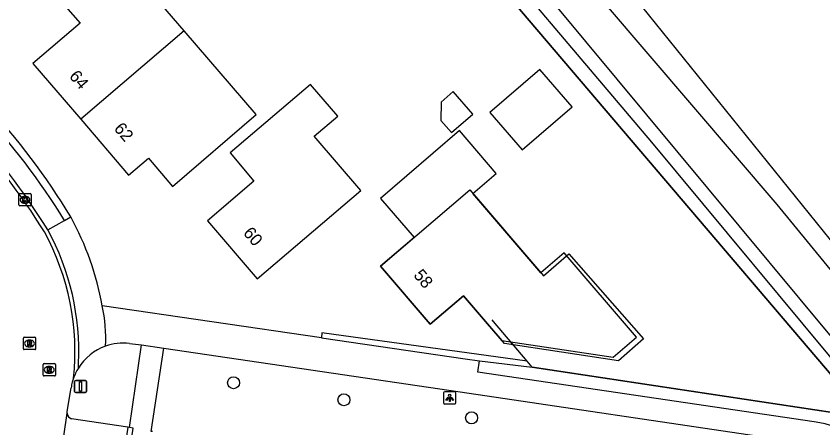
# Model space of a CAD drawing. Extents: x 164150 to 165261, y 382513 to 383432.
# Drawn here: x 164601.5 to 164667.2, y 383211.9 to 383245.5 of the extents above; entities that cross this region are included whole.
import ezdxf

# ---------------------------------------------------------------- set-up
doc = ezdxf.new("R2010")
doc.units = 0
for name, color, linetype in [('IMGEO_Afsluitpaal', 7, 'Continuous'), ('IMGEO_Boom', 7, 'Continuous'), ('IMGEO_Groenvoorziening', 7, 'Continuous'), ('IMGEO_Haag', 7, 'Continuous'), ('IMGEO_Hek', 7, 'Continuous'), ('IMGEO_Kolk', 7, 'Continuous'), ('IMGEO_Lichtpunt', 7, 'Continuous'), ('IMGEO_Pand', 7, 'Continuous'), ('IMGEO_Pand_nummerreeks', 7, 'Continuous'), ('IMGEO_Pand_vergunning_verleend', 7, 'Continuous'), ('IMGEO_Parkeervlak_open', 7, 'Continuous'), ('IMGEO_Rijbaan_lokaal_open', 7, 'Continuous'), ('IMGEO_Rioolput', 7, 'Continuous'), ('IMGEO_Voetpad_open', 7, 'Continuous'), ('IMGEO_Waterloop', 7, 'Continuous')]:
    doc.layers.add(name, color=color, linetype=linetype)

msp = doc.modelspace()

# ---------------------------------------------------------------- linework, layer by layer
at = {"layer": 'IMGEO_Afsluitpaal'}
for p, q in [((164606.376, 383215.801), (164607.166, 383215.801)), ((164607.166, 383215.801), (164606.376, 383215.801)), ((164606.276, 383214.901), (164606.276, 383215.701)), ((164606.276, 383215.701), (164606.276, 383214.901)), ((164607.266, 383215.701), (164607.266, 383214.901)), ((164607.266, 383214.901), (164607.266, 383215.701)), ((164607.166, 383214.801), (164606.376, 383214.801)), ((164606.376, 383214.801), (164607.166, 383214.801))]:
    msp.add_line(p, q, dxfattribs=at)
msp.add_lwpolyline([(164606.696, 383215.676), (164606.846, 383215.676), (164606.846, 383214.926), (164606.696, 383214.926), (164606.696, 383215.676)], dxfattribs=at)
for centre, start, end in [((164606.376, 383215.701), 90, 180), ((164606.376, 383215.701), 90, 180), ((164607.166, 383215.701), 0, 90), ((164607.166, 383215.701), 360, 90), ((164606.376, 383214.901), 180, 270), ((164606.376, 383214.901), 180, 270), ((164607.166, 383214.901), 270, 0), ((164607.166, 383214.901), 270, 0)]:
    msp.add_arc(centre, 0.1, start, end, dxfattribs=at)
at = {"layer": 'IMGEO_Boom'}
for centre in [(164619.226, 383215.605), (164628.209, 383214.22), (164638.607, 383212.751)]:
    msp.add_circle(centre, 0.489, dxfattribs=at)
at = {"layer": 'IMGEO_Groenvoorziening'}
for points in [[(164566.305, 383344.311), (164569.232, 383342.658), (164579.791, 383329.652), (164603.14, 383303.958), (164617.977, 383286.766), (164648.404, 383251.254), (164673.485, 383220.184), (164709.708, 383176.739), (164710.441, 383175.86), (164752.593, 383124.39), (164776.716, 383094.655), (164796.852, 383070.221), (164805.188, 383059.841), (164822.836, 383038.617), (164858.114, 382995.014), (164877.754, 382971.302), (164899.005, 382944.896), (164903.538, 382938.379)], [(164565.515, 383339.104), (164586.345, 383315.663), (164606.03, 383291.593), (164619.657, 383274.842), (164653.254, 383235.189), (164669.707, 383215.37), (164689.184, 383191.909), (164697.544, 383182.287), (164699.35, 383180.017), (164699.148, 383178.489), (164689.54, 383169.792), (164688.541, 383168.421), (164688.591, 383167.263)], [(164643.541, 383216.874), (164670.853, 383212.753), (164601.938, 383293.634), (164580.845, 383318.389), (164573.491, 383327.02), (164568.932, 383331.938), (164563.693, 383332.71)]]:
    msp.add_lwpolyline(points, dxfattribs=at)
at = {"layer": 'IMGEO_Haag'}
for points in [[(164643.541, 383216.874), (164643.122, 383217.367), (164626.412, 383219.679), (164626.392, 383219.249)], [(164639.25, 383217.382), (164643.541, 383216.874)]]:
    msp.add_lwpolyline(points, dxfattribs=at)
at = {"layer": 'IMGEO_Hek'}
msp.add_lwpolyline([(164546.01, 383335.315), (164546.486, 383335.245), (164563.693, 383332.71), (164568.932, 383331.938), (164573.491, 383327.02), (164580.845, 383318.389), (164601.938, 383293.634), (164670.853, 383212.753), (164643.541, 383216.874), (164643.122, 383217.367), (164640.381, 383220.598), (164640.269, 383220.73)], dxfattribs=at)
at = {"layer": 'IMGEO_Kolk'}
for p, q in [((164601.745, 383230.077), (164601.745, 383230.929)), ((164601.82, 383231.003), (164602.672, 383231.003)), ((164602.746, 383230.929), (164602.746, 383230.077)), ((164602.233, 383230.783), (164602.258, 383230.783)), ((164602.672, 383230.003), (164601.82, 383230.003)), ((164602.256, 383230.223), (164602.231, 383230.223))]:
    msp.add_line(p, q, dxfattribs=at)
for points in [[(164601.745, 383230.077), (164601.745, 383230.929)], [(164601.82, 383231.003), (164602.672, 383231.003)], [(164602.746, 383230.929), (164602.746, 383230.077)], [(164602.066, 383230.703), (164602.189, 383230.703), (164602.189, 383230.552), (164602.319, 383230.703), (164602.483, 383230.703), (164602.337, 383230.552), (164602.49, 383230.303), (164602.338, 383230.303), (164602.253, 383230.467), (164602.189, 383230.4), (164602.189, 383230.303), (164602.066, 383230.303), (164602.066, 383230.703)], [(164602.672, 383230.003), (164601.82, 383230.003)]]:
    msp.add_lwpolyline(points, dxfattribs=at)
for centre, start, end in [((164601.822, 383230.927), 91.55205, 178.44795), ((164601.822, 383230.927), 91.55205, 178.44795), ((164602.67, 383230.927), 1.55205, 88.44795), ((164602.67, 383230.927), 1.55205, 88.44795), ((164601.822, 383230.079), 181.55205, 268.44795), ((164601.822, 383230.079), 181.55205, 268.44795), ((164602.67, 383230.079), 271.55205, 358.44795), ((164602.67, 383230.079), 271.55205, 358.44795)]:
    msp.add_arc(centre, 0.0765, start, end, dxfattribs=at)
for centre, major_axis, ratio, start_param, end_param in [((164602.232, 383230.503), (-0.387, 0.002), 0.722429, 4.712389, 7.853982), ((164602.257, 383230.503), (-0.39, 0.002), 0.717154, 1.570796, 4.712389)]:
    msp.add_ellipse(centre, major_axis=major_axis, ratio=ratio, start_param=start_param, end_param=end_param, dxfattribs=at)
at = {"layer": 'IMGEO_Lichtpunt'}
for p, q in [((164636.323, 383214.776), (164636.323, 383213.969)), ((164636.323, 383214.776), (164636.323, 383213.969)), ((164637.225, 383214.871), (164636.417, 383214.871)), ((164637.225, 383214.871), (164636.417, 383214.871)), ((164637.319, 383213.969), (164637.319, 383214.776)), ((164637.319, 383213.969), (164637.319, 383214.776)), ((164636.417, 383213.875), (164637.225, 383213.875)), ((164636.417, 383213.875), (164637.225, 383213.875))]:
    msp.add_line(p, q, dxfattribs=at)
for points in [[(164636.697, 383214.44), (164636.736, 383214.412), (164636.548, 383214.15), (164636.51, 383214.177), (164636.697, 383214.44)], [(164636.799, 383214.392), (164636.846, 383214.392), (164636.846, 383214.07), (164636.799, 383214.07), (164636.799, 383214.392)], [(164636.909, 383214.412), (164636.947, 383214.439), (164637.134, 383214.177), (164637.095, 383214.149), (164636.909, 383214.412)]]:
    msp.add_lwpolyline(points, dxfattribs=at)
msp.add_circle((164636.822, 383214.574), 0.0994, dxfattribs=at)
for centre, start, end in [((164636.417, 383214.776), 90, 180), ((164636.417, 383214.776), 90, 180), ((164637.225, 383214.776), 0, 90), ((164637.225, 383214.776), 0, 90), ((164636.417, 383213.969), 180, 270), ((164636.417, 383213.969), 180, 270), ((164637.225, 383213.969), 270, 0), ((164637.225, 383213.969), 270, 360)]:
    msp.add_arc(centre, 0.0946, start, end, dxfattribs=at)
at = {"layer": 'IMGEO_Pand'}
for points in [[(164615.196, 383244.255), (164609.326, 383251.083), (164604.764, 383247.162), (164606.73, 383244.876), (164602.89, 383241.599), (164606.788, 383237.05)], [(164615.196, 383244.255), (164606.788, 383237.05)], [(164606.788, 383237.05), (164610.685, 383232.501), (164612.288, 383233.879), (164614.258, 383231.586), (164621.06, 383237.434), (164615.196, 383244.255)], [(164640.092, 383237.6), (164642.715, 383234.558), (164646.787, 383238.07), (164644.164, 383241.112), (164640.092, 383237.6)], [(164625.794, 383235.67), (164627.701, 383237.298), (164625.487, 383239.892), (164618.944, 383234.31), (164620.872, 383232.014), (164617.103, 383228.793), (164621.15, 383224.053), (164629.573, 383231.245), (164625.794, 383235.67)], [(164636.106, 383236.955), (164636.955, 383235.971), (164638.699, 383237.476), (164637.11, 383239.318), (164636.12, 383238.457), (164636.106, 383236.955)], [(164638.71, 383231.02), (164640.611, 383232.65), (164637.627, 383236.131), (164631.192, 383230.613), (164633.918, 383227.433), (164631.189, 383225.093), (164635.228, 383220.369), (164637.944, 383222.69), (164639.894, 383220.41), (164641.061, 383219.045), (164650.127, 383217.698), (164652.017, 383219.319), (164646.13, 383226.185), (164644.234, 383224.559), (164638.71, 383231.02)]]:
    msp.add_lwpolyline(points, dxfattribs=at)
at = {"layer": 'IMGEO_Pand_vergunning_verleend'}
msp.add_lwpolyline([(164631.189, 383225.093), (164638.453, 383231.321), (164644.45, 383224.306), (164646.506, 383226.111), (164652.588, 383219.183), (164650.552, 383217.395), (164641.272, 383218.799), (164639.894, 383220.41), (164637.944, 383222.69), (164635.228, 383220.369), (164631.189, 383225.093)], dxfattribs=at)
at = {"layer": 'IMGEO_Parkeervlak_open'}
for points in [[(164610.617, 383211.988), (164606.029, 383212.667)], [(164610.617, 383211.988), (164610.18, 383209.062)], [(164610.746, 383211.965), (164610.617, 383211.988)]]:
    msp.add_lwpolyline(points, dxfattribs=at)
msp.add_arc((164606.198, 383213.17), 0.53, 184.81598, 251.36576, dxfattribs=at)
at = {"layer": 'IMGEO_Rijbaan_lokaal_open'}
for points in [[(164606.59, 383216.789), (164606.612, 383217.186)], [(164605.67, 383213.125), (164605.687, 383213.224), (164605.822, 383214.068), (164606.002, 383215.195)], [(164605.131, 383209.378), (164605.67, 383213.125)]]:
    msp.add_lwpolyline(points, dxfattribs=at)
for centre, radius, start, end in [((164553.959, 383196.796), 58.767, 31.95015, 42.60844), ((164554.106, 383196.908), 58.905, 31.93315, 42.61737), ((164585.903, 383218.131), 20.408, 353.90734, 28.58319), ((164585.916, 383218.132), 20.717, 357.38349, 28.65036), ((164610.118, 383214.596), 4.154, 148.13366, 160.75625), ((164610.329, 383214.517), 4.38, 160.6948, 165.0491), ((164610.343, 383214.509), 4.395, 164.99587, 171.02246)]:
    msp.add_arc(centre, radius, start, end, dxfattribs=at)
at = {"layer": 'IMGEO_Rioolput'}
for p, q in [((164602.114, 383218.377), (164602.114, 383219.229)), ((164602.189, 383219.303), (164603.041, 383219.303)), ((164602.602, 383219.083), (164602.627, 383219.083)), ((164603.115, 383219.229), (164603.115, 383218.377)), ((164602.625, 383218.523), (164602.6, 383218.523)), ((164603.041, 383218.303), (164602.189, 383218.303)), ((164603.794, 383217.159), (164604.646, 383217.159)), ((164603.719, 383216.233), (164603.719, 383217.085)), ((164604.207, 383216.939), (164604.232, 383216.939)), ((164604.72, 383217.085), (164604.72, 383216.233)), ((164604.646, 383216.159), (164603.794, 383216.159)), ((164604.23, 383216.379), (164604.205, 383216.379))]:
    msp.add_line(p, q, dxfattribs=at)
for points in [[(164602.114, 383218.377), (164602.114, 383219.229)], [(164602.189, 383219.303), (164603.041, 383219.303)], [(164603.115, 383219.229), (164603.115, 383218.377)], [(164602.703, 383219.001), (164602.451, 383219.003), (164602.451, 383218.603)], [(164602.451, 383218.603), (164602.575, 383218.603), (164602.575, 383218.765), (164602.586, 383218.765)], [(164602.629, 383218.922), (164602.575, 383218.922), (164602.575, 383218.841)], [(164602.575, 383218.841), (164602.627, 383218.841)], [(164602.633, 383218.736), (164602.704, 383218.603), (164602.844, 383218.603), (164602.779, 383218.729)], [(164603.041, 383218.303), (164602.189, 383218.303)], [(164603.794, 383217.159), (164604.646, 383217.159)], [(164603.719, 383216.233), (164603.719, 383217.085)], [(164604.308, 383216.857), (164604.056, 383216.859), (164604.056, 383216.459)], [(164604.056, 383216.459), (164604.18, 383216.459), (164604.18, 383216.621), (164604.191, 383216.621)], [(164604.234, 383216.778), (164604.18, 383216.778), (164604.18, 383216.697)], [(164604.18, 383216.697), (164604.232, 383216.697)], [(164604.238, 383216.592), (164604.309, 383216.459), (164604.449, 383216.459), (164604.384, 383216.585)], [(164604.72, 383217.085), (164604.72, 383216.233)], [(164604.646, 383216.159), (164603.794, 383216.159)]]:
    msp.add_lwpolyline(points, dxfattribs=at)
for centre, radius, start, end in [((164602.191, 383219.227), 0.0765, 91.55205, 178.44795), ((164602.191, 383219.227), 0.0765, 91.55205, 178.44795), ((164603.039, 383219.227), 0.0765, 1.55205, 88.44795), ((164603.039, 383219.227), 0.0765, 1.55205, 88.44795), ((164602.585, 383218.712), 0.0533, 26.02933, 88.69889), ((164602.611, 383219.03), 0.19, 274.7715, 282.96867), ((164602.635, 383218.826), 0.0964, 77.00612, 93.18647), ((164602.649, 383218.883), 0.0378, 276.66336, 79.67722), ((164602.702, 383218.891), 0.109, 350.36119, 89.41601), ((164602.7, 383218.891), 0.112, 277.58423, 350.98172), ((164602.684, 383218.676), 0.108, 29.51342, 73.79051), ((164602.191, 383218.379), 0.0765, 181.55205, 268.44795), ((164602.191, 383218.379), 0.0765, 181.55205, 268.44795), ((164603.039, 383218.379), 0.0765, 271.55205, 358.44795), ((164603.039, 383218.379), 0.0765, 271.55205, 358.44795), ((164603.796, 383217.083), 0.0765, 91.55205, 178.44795), ((164603.796, 383217.083), 0.0765, 91.55205, 178.44795), ((164604.644, 383217.083), 0.0765, 1.55205, 88.44795), ((164604.644, 383217.083), 0.0765, 1.55205, 88.44795), ((164604.19, 383216.568), 0.0533, 26.02933, 88.69889), ((164604.216, 383216.886), 0.19, 274.7715, 282.96867), ((164604.24, 383216.682), 0.0964, 77.00612, 93.18647), ((164604.254, 383216.739), 0.0378, 276.66336, 79.67722), ((164604.307, 383216.747), 0.109, 350.36119, 89.41601), ((164604.305, 383216.747), 0.112, 277.58423, 350.98172), ((164604.289, 383216.532), 0.108, 29.51342, 73.79051), ((164603.796, 383216.235), 0.0765, 181.55205, 268.44795), ((164603.796, 383216.235), 0.0765, 181.55205, 268.44795), ((164604.644, 383216.235), 0.0765, 271.55205, 358.44795), ((164604.644, 383216.235), 0.0765, 271.55205, 358.44795)]:
    msp.add_arc(centre, radius, start, end, dxfattribs=at)
for centre, major_axis, ratio, start_param, end_param in [((164602.601, 383218.803), (-0.387, 0.002), 0.722429, 4.712389, 7.853982), ((164602.626, 383218.803), (-0.39, 0.002), 0.717154, 1.570796, 4.712389), ((164604.206, 383216.659), (-0.387, 0.002), 0.722429, 4.712389, 7.853982), ((164604.231, 383216.659), (-0.39, 0.002), 0.717154, 1.570796, 4.712389)]:
    msp.add_ellipse(centre, major_axis=major_axis, ratio=ratio, start_param=start_param, end_param=end_param, dxfattribs=at)
at = {"layer": 'IMGEO_Voetpad_open'}
for points in [[(164605.468, 383228.825), (164605.966, 383229.101)], [(164604.097, 383228.065), (164605.468, 383228.825)], [(164626.392, 383219.249), (164608.532, 383221.856)], [(164626.392, 383219.249), (164638.066, 383217.545), (164639.25, 383217.382)], [(164610.746, 383218.807), (164611.741, 383218.681)], [(164610.746, 383211.965), (164611.741, 383218.681)], [(164611.741, 383218.681), (164613.544, 383218.419)], [(164612.63, 383211.627), (164612.515, 383211.648), (164613.544, 383218.419)], [(164613.544, 383218.419), (164637.668, 383214.862), (164662.565, 383211.164)], [(164666.489, 383212.417), (164639.122, 383216.472), (164639.25, 383217.382)], [(164610.18, 383209.062), (164610.616, 383208.973), (164611.052, 383211.91), (164610.746, 383211.965)]]:
    msp.add_lwpolyline(points, dxfattribs=at)
for centre, radius, start, end in [((164559.353, 383201.093), 54.381, 31.0002, 43.12082), ((164554.87, 383197.417), 59.554, 31.829, 42.75747), ((164585.722, 383217.854), 23.158, 9.95074, 29.05503), ((164597.282, 383219.297), 11.538, 356.43992, 12.81222), ((164610.252, 383214.534), 4.301, 109.77624, 148.37433), ((164610.253, 383214.546), 4.29, 83.3937, 109.8349), ((164665.178, 383202.962), 9.545, 38.52029, 82.10627)]:
    msp.add_arc(centre, radius, start, end, dxfattribs=at)
at = {"layer": 'IMGEO_Waterloop'}
msp.add_lwpolyline([(164702.895, 383175.561), (164691.673, 383166.485), (164690.67, 383167.345), (164701.976, 383176.715), (164702.796, 383177.395), (164568.021, 383339.417), (164569.063, 383340.332), (164663.446, 383230.119), (164829.318, 383027.736), (164900.978, 382938.587), (164899.829, 382937.694), (164835.51, 383016.034), (164740.957, 383131.523), (164703.749, 383176.252), (164702.895, 383175.561)], dxfattribs=at)

# ---------------------------------------------------------------- texts
at = {"layer": 'IMGEO_Pand_nummerreeks'}
for s, rotation, p in [('64', 310.39331, (164605.788, 383240.526)), ('62', 310.39331, (164609.436, 383236.269)), ('60', 310.29018, (164619.955, 383227.768)), ('58', 310.33029, (164633.822, 383224.327))]:
    msp.add_text(s, height=1, rotation=rotation, dxfattribs=at).set_placement(p)

doc.saveas('drawing.dxf')
